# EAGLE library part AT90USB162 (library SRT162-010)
AT90USB162 Atmel AVR
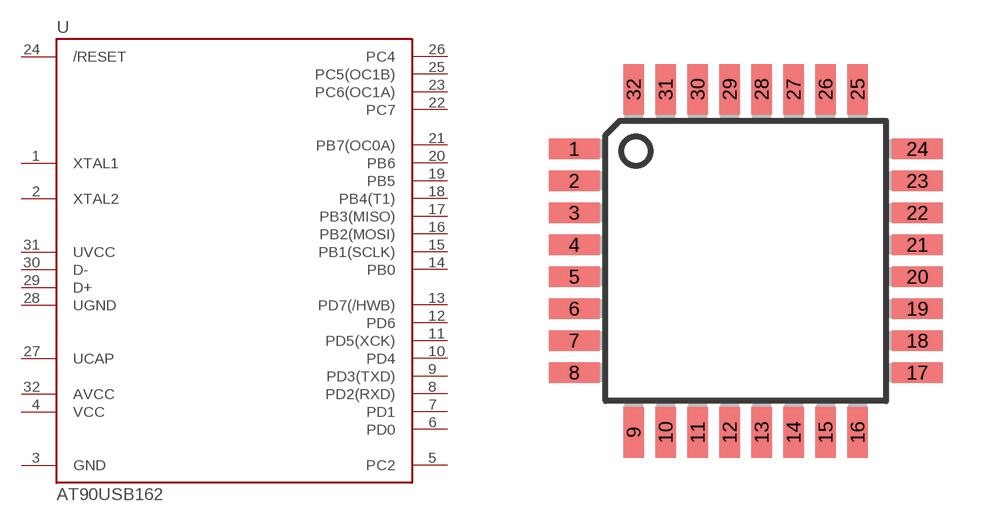
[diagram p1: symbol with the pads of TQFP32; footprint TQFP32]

Designator prefix U

## AT90USB162"  [TQFP32]
1  XTAL1
2  XTAL2
3  GND  pwr
4  VCC  in
5  PC2
6  PD0
7  PD1
8  PD2(RXD)
9  PD3(TXD)
10  PD4
11  PD5(XCK)
12  PD6
13  PD7(/HWB)
14  PB0
15  PB1(SCLK)
16  PB2(MOSI)
17  PB3(MISO)
18  PB4(T1)  pas
19  PB5  pas
20  PB6  pas
21  PB7(OC0A)
22  PC7
23  PC6(OC1A)
24  /RESET
25  PC5(OC1B)
26  PC4
27  UCAP  pas
28  UGND  pas
29  D+
30  D-
31  UVCC  pas
32  AVCC  in

## Footprint TQFP32 (pad centres in mm)
smd 1.27 x 0.508: 1 -4.293,2.8; 2 -4.293,2; 3 -4.293,1.2; 4 -4.293,0.4; 5 -4.293,-0.4; 6 -4.293,-1.2; 7 -4.293,-2; 8 -4.293,-2.8; 17 4.293,-2.8; 18 4.293,-2; 19 4.293,-1.2; 20 4.293,-0.4; 21 4.293,0.4; 22 4.293,1.2; 23 4.293,2; 24 4.293,2.8
smd 0.508 x 1.27: 9 -2.8,-4.293; 10 -2,-4.293; 11 -1.2,-4.293; 12 -0.4,-4.293; 13 0.4,-4.293; 14 1.2,-4.293; 15 2,-4.293; 16 2.8,-4.293; 25 2.8,4.293; 26 2,4.293; 27 1.2,4.293; 28 0.4,4.293; 29 -0.4,4.293; 30 -1.2,4.293; 31 -2,4.293; 32 -2.8,4.293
